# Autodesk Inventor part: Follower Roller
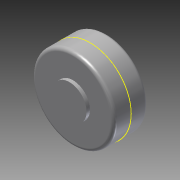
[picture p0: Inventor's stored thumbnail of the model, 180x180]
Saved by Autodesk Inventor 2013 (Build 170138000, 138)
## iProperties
Created: 2008-07
Part Number: Follower Roller
Document SubType Name: Modeling
Designer: tangg
Density: 7.85 g/cm^3
Material: Alloy Steel
Author: tangg
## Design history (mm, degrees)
feature "Base1"
sketch "Sketch1"
  geometry: C1 r 3.81 at (0, 0) reference; 1 further point
  constraints: 1 other
  node "Project Cut Edges1"
body "Solid1"
